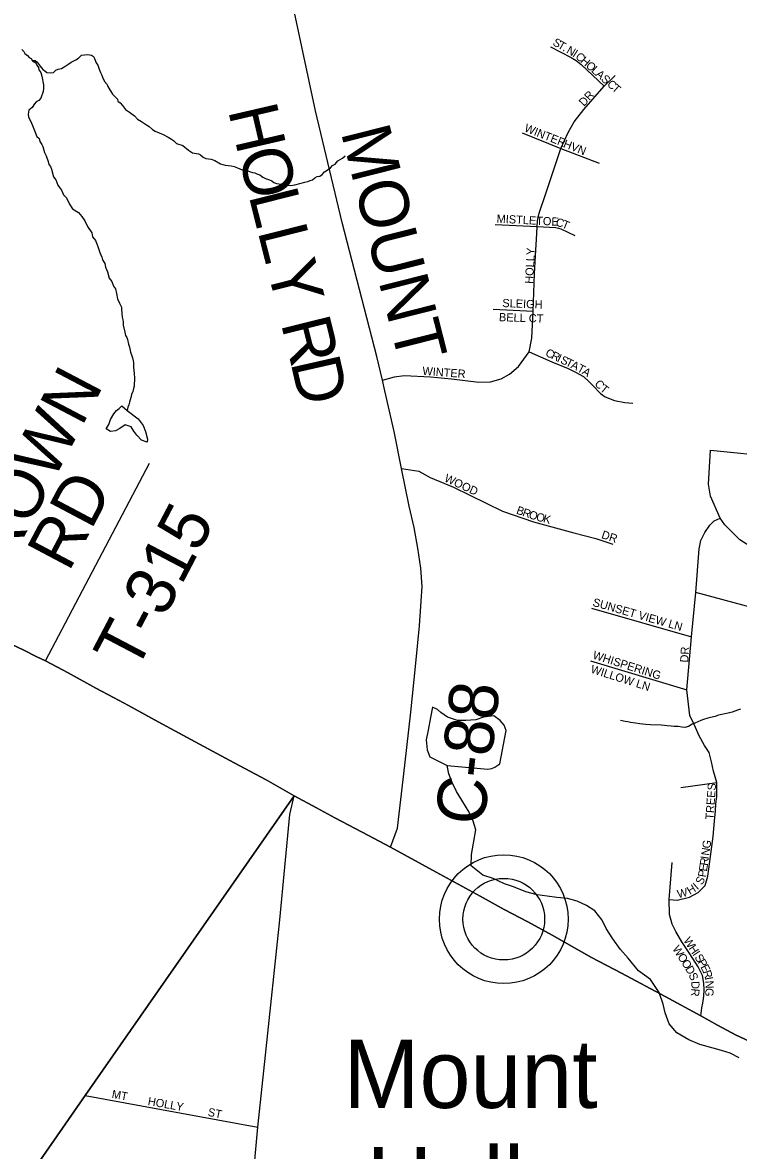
# Model space of a CAD drawing. Extents: x 1310247 to 1664935, y 235267 to 584339.
# Drawn here: x 1488461 to 1492826, y 371649 to 378528 of the extents above; entities that cross this region are included whole.
import ezdxf

# ---------------------------------------------------------------- set-up
doc = ezdxf.new("R2010")
doc.units = 0
for name, color, linetype in [('GM_X_County_Road', 7, 'Continuous'), ('GM_X_County_Road_Text', 7, 'Continuous'), ('GM_X_Minor_Lake', 7, 'Continuous'), ('GM_X_Minor_River', 7, 'Continuous'), ('GM_X_State_Route', 7, 'Continuous'), ('GM_X_Township', 7, 'Continuous'), ('GM_X_Township_Road', 7, 'Continuous'), ('GM_X_Township_Road_Text', 7, 'Continuous'), ('GM_X_Township_Subdivision', 7, 'Continuous'), ('GM_X_Township_Subdivision_Text', 7, 'Continuous'), ('GM_X_Unincorporated', 7, 'Continuous'), ('GM_X_Unincorporated_Location', 7, 'Continuous'), ('GM_X_Unincorporated_Text', 7, 'Continuous')]:
    doc.layers.add(name, color=color, linetype=linetype)

msp = doc.modelspace()

# ---------------------------------------------------------------- linework, layer by layer
at = {"layer": 'GM_X_County_Road'}
for points in [[(1490704.7, 373498.3), (1490746.7, 373613.8), (1490792.7, 373999.5), (1490828.5, 374322.3), (1490859.3, 374622), (1490881.9, 374849.1), (1490897.7, 375088.3), (1490889.4, 375201.2), (1490872.1, 375321.6), (1490849.2, 375448.9), (1490819.4, 375578.5), (1490772.5, 375808.3), (1490726.5, 376033.9), (1490670.3, 376282.7), (1490655.4, 376347.1), (1490622.1, 376491.5), (1490409.9, 377308.1), (1490247.1, 377989.3), (1490125.5, 378560.5), (1490092.3, 378709.6), (1490080.8, 378810.5), (1490081.9, 378913.7), (1490306.8, 380908)], [(1492812.6, 369012.2), (1492696, 369031.9), (1492229.7, 369084.2), (1490843, 369253.7), (1490689.1, 369274.6), (1490522, 369296.3), (1490398.3, 369308), (1490341.4, 369316.4), (1490214.4, 369368.2), (1489923.6, 369480.1), (1489681.2, 369590.4), (1489709.7, 369857.9), (1489763.1, 370459.6), (1489863.4, 371430.7), (1489895.6, 371790.4), (1489943.3, 372229.5), (1490029, 373055.8), (1490091.8, 373698.7), (1490116.8, 373811.7)]]:
    msp.add_lwpolyline(points, dxfattribs=at)
at = {"layer": 'GM_X_Minor_Lake'}
for points in [[(1488997.8, 376033.6), (1488972, 376050.1), (1488986.4, 376076), (1488997, 376107.9), (1489017.7, 376141.6), (1489034.1, 376161.4), (1489050.4, 376175.2), (1489066.7, 376191), (1489099.7, 376162.9)], [(1489099.7, 376162.9), (1489165.7, 376111), (1489197.1, 376070.3), (1489210.6, 376033.9), (1489223.8, 375987.5), (1489221.5, 375969.5), (1489185.6, 375982.2), (1489158, 376010.8), (1489140.4, 376037.1), (1489122.7, 376063.5), (1489086.8, 376074.2), (1489054.3, 376052.7), (1489028, 376039.1), (1488997.8, 376033.6)], [(1490960.6, 374353.6), (1490949.4, 374289.6), (1490934.1, 374213.5), (1490923, 374153.5), (1490928, 374093.2), (1490945.4, 374050.8), (1491050.8, 373996.8)], [(1491050.8, 373996.8), (1491297.4, 373974.4), (1491321.5, 373978), (1491341.8, 373987.7), (1491372.2, 374007.2), (1491409.8, 374211.3), (1491398.3, 374243.6), (1491372.7, 374272.2), (1491335, 374298.9), (1491270.7, 374292), (1491224.2, 374274.8), (1491163.9, 374271.8), (1491113.7, 374270.6), (1491075.8, 374283.3), (1491051.9, 374291.8), (1491012.2, 374320.6), (1490990.4, 374339), (1490960.6, 374353.6)]]:
    msp.add_lwpolyline(points, dxfattribs=at)
at = {"layer": 'GM_X_Minor_River'}
for points in [[(1488456.3, 378363.4), (1488468.1, 378351.1), (1488476, 378339), (1488491.8, 378326.6), (1488501.7, 378314.4), (1488513.6, 378308.2), (1488521.4, 378294), (1488541.2, 378281.6), (1488549, 378267.4), (1488558.9, 378255.1), (1488560.6, 378239), (1488572.4, 378222.8), (1488578, 378200.6)], [(1488520.1, 378296.2), (1488537.5, 378297.7), (1488549.4, 378287.4), (1488569, 378263), (1488584.7, 378242.6), (1488596.7, 378234.4), (1488608.5, 378224.1), (1488632.6, 378221.7), (1488650.7, 378223.4), (1488664.9, 378237.2), (1488679.1, 378243), (1488699.3, 378248.6), (1488725.6, 378264.3), (1488737.8, 378272.1), (1488758.1, 378285.8), (1488770.3, 378293.6), (1488786.5, 378301.3), (1488802.7, 378311.1), (1488821.1, 378328.8), (1488857.3, 378334.2), (1488881.3, 378329.8), (1488893.2, 378321.6), (1488899, 378309.4), (1488910.6, 378283.1), (1488920.4, 378268.9), (1488928, 378244.6), (1488935.7, 378224.4), (1488943.5, 378212.2), (1488949.3, 378196.1), (1488960.9, 378169.7), (1488976.6, 378151.4), (1488980.4, 378137.3), (1489009.7, 378090.6), (1489039.4, 378061.9), (1489043.1, 378047.8), (1489057, 378039.5), (1489070.8, 378023.2), (1489088.5, 377998.8), (1489112.3, 377982.3), (1489144, 377959.7), (1489161.8, 377939.3), (1489185.6, 377924.8), (1489217.4, 377904.1), (1489233.2, 377893.8), (1489253, 377875.4), (1489268.9, 377865.1), (1489318.8, 377846.1), (1489348.6, 377829.5), (1489368.4, 377817.1), (1489382.4, 377808.8), (1489400.1, 377790.5), (1489438, 377777.8), (1489473.7, 377749), (1489497.5, 377734.5), (1489533.6, 377727.9), (1489545.5, 377721.6), (1489563.3, 377707.3), (1489579.2, 377699), (1489611.3, 377694.4), (1489633.2, 377686), (1489669, 377667.2), (1489697, 377658.7), (1489733, 377654.1), (1489751, 377649.7), (1489771, 377641.3), (1489800.9, 377630.8), (1489832.9, 377624.2), (1489862.8, 377613.6), (1489876.8, 377611.4), (1489888.8, 377605.1), (1489908.8, 377598.8), (1489926.6, 377584.4), (1489942.5, 377576.1), (1489966.5, 377569.6), (1489980.4, 377563.4), (1489994.3, 377553.1), (1490010.2, 377546.8), (1490040.3, 377542.2), (1490056.3, 377539.9), (1490078.3, 377535.5), (1490094.4, 377535.2), (1490120.5, 377538.8), (1490152.8, 377546.3), (1490183, 377553.8), (1490201.2, 377559.5), (1490215.3, 377565.3), (1490229.4, 377569), (1490243.7, 377580.8), (1490257.8, 377588.6), (1490274, 377592.3), (1490288.2, 377602.1), (1490302.5, 377617.9), (1490324.8, 377631.6), (1490339, 377641.4), (1490351.3, 377657.3), (1490367.5, 377665), (1490383.9, 377684.8), (1490412.3, 377700.4), (1490428.6, 377716.1)], [(1488578, 378200.6), (1488589.2, 378148.2), (1488588.8, 378126.1), (1488586.5, 378108), (1488571.7, 378066.1), (1488561.5, 378052.2), (1488543.3, 378044.5), (1488535, 378032.6), (1488520.6, 378010.8), (1488500.2, 377993.1), (1488495.8, 377969), (1488497.5, 377950.9), (1488511.1, 377924.6), (1488526.6, 377890.2), (1488547.7, 377833.6), (1488561.6, 377821.3), (1488567.3, 377803.1), (1488579, 377784.8), (1488584.9, 377772.7), (1488594.3, 377736.3), (1488606, 377716.1), (1488617.5, 377681.7), (1488621.1, 377661.6), (1488631, 377649.3), (1488638.7, 377633.1), (1488650, 377586.8), (1488663.7, 377568.4), (1488677.2, 377536.1), (1488687, 377521.8), (1488698.8, 377505.6), (1488710.4, 377477.2), (1488730.1, 377458.8), (1488747.5, 377420.3), (1488765.1, 377391.9), (1488802.9, 377369.2), (1488822.5, 377344.7), (1488840.2, 377318.3), (1488857.6, 377283.8), (1488883.1, 377245.2), (1488888.7, 377221), (1488906.4, 377198.6), (1488914.1, 377178.4), (1488919.8, 377162.2), (1488933.3, 377125.9), (1488944.8, 377097.5), (1488948.6, 377081.4), (1488962.2, 377059.1), (1488967.9, 377036.9), (1488979.5, 377008.6), (1488988.9, 376970.2), (1489004.6, 376949.9), (1489016.1, 376919.5), (1489027.9, 376903.3), (1489033.4, 376875), (1489040.9, 376842.8), (1489052.5, 376816.5), (1489064.1, 376792.2), (1489063.9, 376780.1), (1489067.5, 376753.9), (1489069.1, 376731.8), (1489072.9, 376715.7), (1489074.7, 376703.6), (1489074.4, 376683.5), (1489085.7, 376639.1), (1489089.3, 376619), (1489097.2, 376606.8), (1489101, 376594.7), (1489106.5, 376566.5), (1489114.2, 376548.2), (1489119.7, 376518), (1489127.4, 376495.8), (1489131.2, 376483.7), (1489134.9, 376465.5), (1489136.7, 376453.5), (1489138.5, 376441.4), (1489138.3, 376429.3), (1489141.6, 376385.1), (1489143.2, 376361), (1489142.3, 376310.8), (1489136, 376288.8), (1489133.7, 376276.8), (1489125.4, 376260.8), (1489123.2, 376246.8), (1489116.8, 376226.9), (1489112.6, 376212.9), (1489108.3, 376196.9), (1489104.1, 376182.9), (1489099.7, 376162.9)], [(1492838.7, 374339.8), (1492820.6, 374334.1), (1492788.3, 374322.6), (1492764.1, 374317), (1492743.9, 374311.3), (1492725.8, 374307.6), (1492703.6, 374304), (1492683.4, 374296.3), (1492655.2, 374288.8), (1492639.1, 374285), (1492612.9, 374277.5), (1492596.7, 374271.7), (1492560.3, 374254.3), (1492544.1, 374248.5), (1492521.8, 374234.9), (1492499.6, 374229.2), (1492481.6, 374231.6), (1492459.6, 374234), (1492433.5, 374234.4), (1492415.5, 374236.7), (1492391.4, 374239.2), (1492375.4, 374241.5), (1492355.3, 374243.8), (1492289.1, 374245), (1492261.1, 374247.5), (1492225, 374250.1), (1492199, 374254.6), (1492168.9, 374259.1), (1492150.9, 374263.5), (1492134.9, 374265.8), (1492106.9, 374272.3)], [(1492831.2, 372213.5), (1492775.5, 372242.6), (1492723.6, 372259.6), (1492671.6, 372272.5), (1492591.7, 372296), (1492523.9, 372323.2), (1492450.4, 372366.7), (1492403.1, 372421.7), (1492380.2, 372488.3), (1492367, 372540.7), (1492342.2, 372613.4), (1492289.3, 372692.6), (1492215.9, 372744.1), (1492153, 372821.5), (1492107.7, 372874.4), (1492060.7, 372939.5), (1492019.6, 373002.4), (1491994.3, 373053), (1491951.1, 373110), (1491899.5, 373143), (1491843.8, 373170.1), (1491783.8, 373185.1), (1491719.7, 373192.3), (1491659.6, 373199.3), (1491599.5, 373208.4), (1491529.5, 373225.7), (1491453.8, 373257.1), (1491399.9, 373276.1), (1491330.2, 373307.4), (1491268.3, 373328.6), (1491197, 373386), (1491198.2, 373454.2), (1491211.4, 373524.3), (1491224.8, 373604.3), (1491209.7, 373656.8), (1491184.5, 373711.4), (1491139.6, 373786.5), (1491106.4, 373839.2), (1491081.2, 373893.8), (1491060, 373946.4), (1491050.8, 373996.8)]]:
    msp.add_lwpolyline(points, dxfattribs=at)
at = {"layer": 'GM_X_State_Route'}
for points in [[(1487402.8, 375058.2), (1487402.8, 375058.2), (1487497.7, 375033.2), (1487620.7, 374997), (1487751.1, 374961.5), (1487901.6, 374914.6), (1488069.5, 374861.6), (1488252.4, 374795.4), (1488362.2, 374751.7), (1488468.3, 374701.2), (1488543.8, 374662.5), (1488600.8, 374636)], [(1488600.8, 374636), (1488739.8, 374562), (1488908.4, 374469.6), (1489015.1, 374412.2), (1489027.9, 374405.4)], [(1489027.9, 374405.4), (1489107.5, 374363.5), (1489288.5, 374262.4), (1489540.1, 374127.5), (1489751.6, 374013.3), (1489945.8, 373909.7), (1490116.8, 373811.7), (1490254.1, 373738), (1490365.2, 373678.7), (1490532.4, 373590), (1490704.7, 373498.3), (1490982.9, 373345.8), (1491250.5, 373200.6), (1491395.9, 373120.5)], [(1491395.9, 373120.5), (1491397.4, 373119.7), (1491541.7, 373043), (1491689.8, 372961.5), (1491930.6, 372825.1), (1492113.4, 372731.3), (1492378.8, 372588.3), (1492596.3, 372470.1), (1492698.2, 372413.5), (1492812.6, 372351.5), (1493014.5, 372259.3), (1493112.5, 372224.6), (1493205.8, 372182.9), (1493369.5, 372118.3), (1493457, 372080)]]:
    msp.add_lwpolyline(points, dxfattribs=at)
at = {"layer": 'GM_X_Township'}
for points in [[(1488362.2, 374751.7), (1488468.3, 374701.2), (1488543.9, 374662.5), (1488600.8, 374636), (1488739.9, 374562), (1488908.4, 374469.6), (1489015.1, 374412.2), (1489107.5, 374363.5), (1489288.5, 374262.4), (1489540.1, 374127.5), (1489751.7, 374013.3), (1489945.8, 373909.7), (1490116.8, 373811.7), (1488843.4, 371983.4), (1487862.5, 370575)], [(1493014.5, 372259.3), (1492812.6, 372351.5), (1492698.2, 372413.5), (1492596.3, 372470.1), (1492378.8, 372588.3), (1492113.4, 372731.3), (1491930.6, 372825.1), (1491689.8, 372961.5), (1491541.8, 373043), (1491397.4, 373119.7), (1491250.5, 373200.6), (1490982.9, 373345.8), (1490704.7, 373498.3), (1490532.4, 373590), (1490365.2, 373678.7), (1490254.1, 373738), (1490116.8, 373811.7), (1489945.8, 373909.7), (1489751.7, 374013.3), (1489540.1, 374127.5), (1489288.5, 374262.4), (1489107.5, 374363.5), (1489015.1, 374412.2), (1488908.4, 374469.6), (1488739.9, 374562), (1488600.8, 374636), (1488543.9, 374662.5), (1488468.3, 374701.2), (1488362.2, 374751.7)], [(1487862.5, 370575), (1488843.4, 371983.4), (1490116.8, 373811.7), (1490254.1, 373738), (1490365.2, 373678.7), (1490532.4, 373590), (1490704.7, 373498.3), (1490982.9, 373345.8), (1491250.5, 373200.6), (1491397.4, 373119.7), (1491541.8, 373043), (1491689.8, 372961.5), (1491930.6, 372825.1), (1492113.4, 372731.3), (1492378.8, 372588.3), (1492596.3, 372470.1), (1492698.2, 372413.5), (1492812.6, 372351.5), (1493014.5, 372259.3)]]:
    msp.add_lwpolyline(points, dxfattribs=at)
at = {"layer": 'GM_X_Township_Road'}
msp.add_lwpolyline([(1488600.8, 374636), (1489235.9, 375841.3)], dxfattribs=at)
at = {"layer": 'GM_X_Township_Subdivision'}
for points in [[(1491680.1, 378380.2), (1491806.2, 378315.8), (1491835.7, 378296.4), (1491866.5, 378272.9), (1492008, 378139.4)], [(1490655.4, 376347.1), (1490728.5, 376367.4), (1490788, 376376.6), (1490949.1, 376367.4), (1491075.9, 376355.5), (1491243.7, 376335.7), (1491315, 376337), (1491379.7, 376355.5), (1491431.2, 376384.5), (1491485.4, 376430.8), (1491550.1, 376519.3), (1491567.3, 376603.8), (1491574, 376768.9), (1491583.2, 376995.5), (1491589.4, 377105.7), (1491596.3, 377241.9), (1491599.7, 377284.9), (1491601.5, 377319.4), (1491610.1, 377365.9), (1491653.2, 377491.7), (1491742.8, 377760.4), (1491787.5, 377856.9), (1491825.4, 377922.4), (1491884, 377998.2), (1492008, 378139.4), (1492075.2, 378204.9)], [(1491508.3, 377855), (1491742.8, 377760.4), (1491976.5, 377671.2)], [(1491342.7, 377295.6), (1491599.7, 377284.9), (1491712.2, 377277.5), (1491729.7, 377274.8), (1491743.8, 377270.7), (1491827.6, 377229.2)], [(1491331.3, 376779.9), (1491574, 376768.9)], [(1491550.1, 376519.3), (1491688.8, 376459.8), (1491787.9, 376417.6), (1491832.8, 376395.1), (1491880.4, 376368.7), (1491914.1, 376339.1), (1491938.5, 376314.5), (1491984.7, 376265.7), (1492013.8, 376245.8), (1492070.6, 376223.4), (1492132.7, 376211.5), (1492181.5, 376206.2)], [(1493478.3, 375151.7), (1492933.4, 375309.7), (1492833.6, 375374.2), (1492742.8, 375463.8), (1492714.3, 375505.3), (1492655.9, 375640.6), (1492644.3, 375713), (1492655.9, 375920.7), (1493463.7, 375837.9), (1493576, 375796.3), (1493696.3, 375783.9)], [(1490772.5, 375808.3), (1490878.4, 375791.3), (1490946.7, 375752.9), (1491089, 375694.6), (1491386.6, 375547.9), (1491575.9, 375483.9), (1491822.1, 375415.6), (1491956.5, 375380.7), (1492060.8, 375347.4)], [(1492403.2, 373179.3), (1492453.5, 373175.8), (1492527.4, 373193.7), (1492579.8, 373223.2), (1492624, 373264.9), (1492640.4, 373321.7), (1492651.7, 373411.3), (1492671.9, 373564), (1492679.5, 373657.5), (1492687.1, 373720.6), (1492688.3, 373763.5), (1492693.4, 373807.7), (1492694.6, 373845.5), (1492693.4, 373892.3), (1492674.4, 373961.7), (1492661.8, 374019.8), (1492646.7, 374075.3), (1492618.9, 374118.2), (1492586.1, 374178.8), (1492555.8, 374247), (1492530.5, 374302.5), (1492510.8, 374457.8), (1492540.7, 374781.4), (1492565.6, 375051.4), (1492586.5, 375317.9), (1492597, 375370.1), (1492622.1, 375418.4), (1492652.1, 375462.8), (1492677.2, 375488.9), (1492714.3, 375505.3)], [(1493192.6, 374883.6), (1492565.6, 375051.4)], [(1491929.7, 374956.4), (1492540.7, 374781.4)], [(1491924.6, 374635.7), (1492510.8, 374457.8)], [(1492475, 373863.2), (1492693.4, 373892.3)], [(1492596.3, 372470.1), (1492603.5, 372518.9), (1492610, 372547.6), (1492614.3, 372589.9), (1492617.9, 372628.7), (1492615.7, 372668.9), (1492607.8, 372717), (1492581.3, 372769.4), (1492529.6, 372847.7), (1492481.5, 372922.4), (1492443.4, 372984.1), (1492421.9, 373030), (1492405.4, 373087.4), (1492403.2, 373179.3), (1492422.6, 373404.8)], [(1488843.4, 371983.3), (1489895.6, 371790.4)]]:
    msp.add_lwpolyline(points, dxfattribs=at)
at = {"layer": 'GM_X_Unincorporated'}
for radius in [392.8, 249]:
    msp.add_circle((1491395.4, 373059.8), radius, dxfattribs=at)
at = {"layer": 'GM_X_Unincorporated_Location'}
msp.add_line((1491395.4, 373059.8), (1491395.4, 373059.8), dxfattribs=at)

# ---------------------------------------------------------------- texts
at = {"layer": 'GM_X_County_Road_Text'}
for s, rotation, p in [('H', 283.04759, (1489713.2, 377994.9)), ('MOUNT', 284.21658, (1490400.8, 377860.8)), ('O', 284.03983, (1489774.1, 377732.2)), ('L', 284.17111, (1489838.4, 377475.3)), ('L', 284.18307, (1489893.3, 377257.7)), ('Y', 284.17584, (1489948.3, 377040.2)), ('R', 283.96999, (1490035.4, 376694.8)), ('D', 282.74178, (1490094.5, 376457.4)), ('C-88', 83.5233, (1491274.3, 373624.8))]:
    msp.add_text(s, height=300, rotation=rotation, dxfattribs=at).set_placement(p)
at = {"layer": 'GM_X_Township_Road_Text'}
for s, rotation, p in [('BROWN', 62.27625, (1488241.4, 374954)), ('RD', 62.10262, (1488742.8, 375171.7)), ('T-315', 62.30639, (1489149.3, 374557.5))]:
    msp.add_text(s, height=300, rotation=rotation, dxfattribs=at).set_placement(p)
at = {"layer": 'GM_X_Township_Subdivision_Text'}
for s, rotation, p in [('S', 330.17039, (1491689.2, 378393.6)), ('T', 330.17039, (1491719.8, 378376.1)), ('.', 330.17568, (1491750.3, 378358.6)), ('N', 330.022, (1491773.2, 378345.5)), ('I', 327.10987, (1491810.7, 378323.9)), ('C', 321.27952, (1491828.1, 378312.7)), ('H', 318.97443, (1491858.6, 378288.3)), ('O', 318.75856, (1491891.8, 378259.4)), ('L', 318.73182, (1491924.9, 378230.4)), ('A', 318.76492, (1491951.3, 378207.2)), ('S', 318.76941, (1491984.4, 378178.2)), ('C', 318.74556, (1492020.8, 378146.3)), ('T', 318.75171, (1492050.6, 378120.1)), ('DR', 47.11989, (1491884.5, 378013.5)), ('WINTER', 338.19935, (1491516.5, 377866.2)), ('HVN', 338.55613, (1491754, 377769.4)), ('MISTLETOE', 357.02789, (1491350.7, 377308)), ('C', 343.98456, (1491708.4, 377290.3)), ('T', 337.48313, (1491745.1, 377279.9)), ('HOLLY', 86.98901, (1491574, 376934)), ('SLEIGH', 357.66397, (1491385.8, 376793.3)), ('BELL CT', 357.95571, (1491365.1, 376707.3)), ('C', 334.41242, (1491644.6, 376497.6)), ('R', 334.41242, (1491680.4, 376480.5)), ('I', 334.4126, (1491716.1, 376463.4)), ('S', 334.41927, (1491735.9, 376453.9)), ('WINTER', 355.75973, (1490897.7, 376379.6)), ('T', 334.43682, (1491767.7, 376438.7)), ('A', 334.2266, (1491799.4, 376423.5)), ('T', 331.55307, (1491838.5, 376404.6)), ('A', 325.64909, (1491868.3, 376388.6)), ('C', 310.15078, (1491945.5, 376323.5)), ('T', 320.68118, (1491978.2, 376286.2)), ('WOOD', 335.22059, (1491028.6, 375732)), ('B', 340.28247, (1491467.8, 375534.3)), ('R', 340.25961, (1491505.1, 375520.9)), ('O', 341.77802, (1491543.7, 375507.1)), ('O', 345.52466, (1491589, 375492.3)), ('K', 345.96178, (1491632, 375481.2)), ('DR', 341.57234, (1491986.8, 375384.8)), ('SUNSET VIEW LN', 344.12322, (1491933.6, 374971.3)), ('DR', 86.98901, (1492520, 374624)), ('WHISPERING', 342.40953, (1491933.8, 374650)), ('WILLOW LN', 342.47567, (1491921.1, 374563.6)), ('TREES', 85.91808, (1492674, 373665.1)), ('G', 81.88502, (1492653.8, 373488.2)), ('N', 81.86371, (1492647.5, 373444.6)), ('E', 81.34473, (1492633.5, 373348.3)), ('R', 81.85482, (1492638.8, 373383.6)), ('I', 81.87581, (1492644.4, 373422.8)), ('P', 80.50985, (1492627.5, 373312.8)), ('H', 31.15395, (1492530.4, 373207.2)), ('I', 41.19603, (1492575.7, 373235.6)), ('S', 60.49845, (1492603.8, 373264.3)), ('W', 13.28191, (1492459, 373187.6)), ('W', 303.12114, (1492488.8, 372930.3)), ('W', 302.87868, (1492421.1, 372879.1)), ('O', 302.89007, (1492452.1, 372831)), ('H', 303.10817, (1492520.1, 372882.4)), ('I', 303.11947, (1492544.1, 372845.5)), ('S', 303.09145, (1492556.1, 372827.1)), ('O', 302.53825, (1492476, 372794.1)), ('D', 300.5664, (1492499.4, 372757.4)), ('P', 301.64331, (1492575.2, 372797.9)), ('E', 296.80939, (1492593.1, 372768.9)), ('S', 292.16167, (1492520.9, 372721.3)), ('R', 288.63459, (1492608.2, 372739.2)), ('I', 280.41825, (1492620.4, 372703.5)), ('D', 273.17135, (1492537.7, 372680.5)), ('G', 265.01132, (1492626.5, 372641.5)), ('N', 272.93008, (1492624.2, 372683.6)), ('R', 264.33289, (1492540.2, 372638.6)), ('MT', 349.2114, (1489002.4, 371970.7)), ('HOLLY', 349.87695, (1489222.2, 371926.7)), ('ST', 348.69567, (1489587.6, 371860.7))]:
    msp.add_text(s, height=50, rotation=rotation, dxfattribs=at).set_placement(p)
at = {"layer": 'GM_X_Unincorporated_Text'}
for s, p in [('Mount', (1490417.4, 371908.4)), ('Holly', (1490558.2, 371252.8))]:
    msp.add_text(s, height=417, rotation=0.00001, dxfattribs=at).set_placement(p)

doc.saveas('drawing.dxf')
